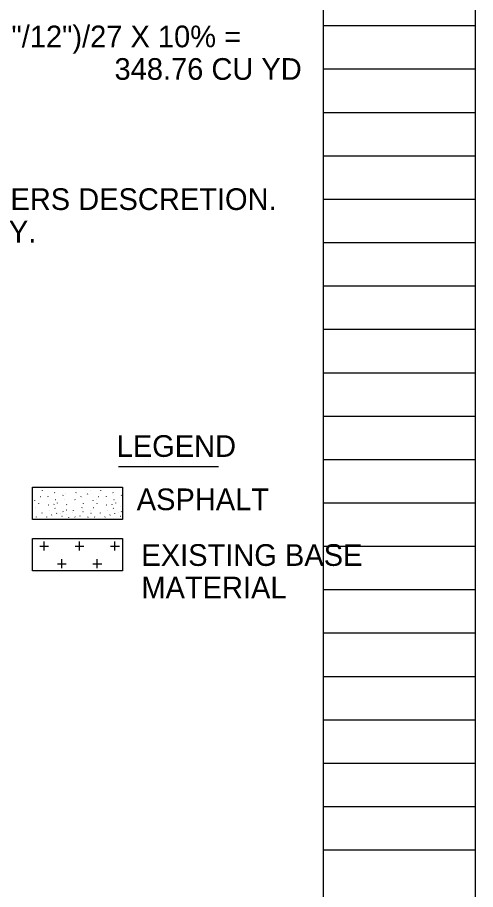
# Model space of a CAD drawing. Extents: x 0 to 34, y 0 to 22.
# Drawn here: x 22.21 to 25.16, y 10.52 to 16.15 of the extents above; entities that cross this region are included whole.
import ezdxf

# ---------------------------------------------------------------- set-up
doc = ezdxf.new("R2010")
doc.units = 0
for name, color, linetype in [('Default', 7, 'Continuous'), ('SH_Data', 7, 'Continuous'), ('SH_Text', 7, 'Continuous')]:
    doc.layers.add(name, color=color, linetype=linetype)

msp = doc.modelspace()

# ---------------------------------------------------------------- linework, layer by layer
at = {"layer": 'Default'}
for p, q in [((22.8569, 13.255), (23.5031, 13.255)), ((22.3542, 13.058), (22.3532, 13.0588)), ((22.3674, 13.0983), (22.3679, 13.1003)), ((22.4039, 13.0603), (22.4044, 13.062)), ((22.4462, 13.0853), (22.4452, 13.0862)), ((22.5, 13.0685), (22.498, 13.0675)), ((22.5185, 13.0802), (22.5175, 13.0813)), ((22.5829, 13.0837), (22.5835, 13.0858)), ((22.6169, 13.06), (22.6149, 13.0597)), ((22.6542, 13.077), (22.6542, 13.077)), ((22.6585, 13.0765), (22.6592, 13.0785)), ((22.6745, 13.1003), (22.6745, 13.1003)), ((22.73, 13.058), (22.729, 13.0588)), ((22.743, 13.0983), (22.7439, 13.1003)), ((22.7795, 13.0603), (22.7804, 13.062)), ((22.8222, 13.0853), (22.8212, 13.0862)), ((22.8759, 13.0685), (22.8739, 13.0675)), ((22.3182, 13.0338), (22.3187, 13.0355)), ((22.3437, 13.013), (22.3442, 13.0148)), ((22.4065, 13.0055), (22.4047, 13.005)), ((22.441, 13.0102), (22.4419, 13.0122)), ((22.453, 13.04), (22.451, 13.0395)), ((22.464, 13.0188), (22.4645, 13.0207)), ((22.5117, 13.041), (22.5109, 13.0422)), ((22.5227, 13.0075), (22.5234, 13.0093)), ((22.578, 13.0398), (22.577, 13.0408)), ((22.631, 13.013), (22.6319, 13.0148)), ((22.6939, 13.0338), (22.6947, 13.0355)), ((22.7144, 13.0385), (22.7144, 13.0385)), ((22.7197, 13.013), (22.7202, 13.0148)), ((22.7824, 13.0055), (22.7805, 13.005)), ((22.8169, 13.0102), (22.8177, 13.0122)), ((22.8289, 13.04), (22.8269, 13.0395)), ((22.8399, 13.0188), (22.8404, 13.0207)), ((22.305, 12.9503), (22.304, 12.9513)), ((22.321, 12.9873), (22.3192, 12.9868)), ((22.3662, 12.9543), (22.3652, 12.9553)), ((22.4129, 12.9695), (22.4134, 12.9712)), ((22.4489, 12.9833), (22.4479, 12.9845)), ((22.4585, 12.9513), (22.459, 12.9533)), ((22.4835, 12.9483), (22.4835, 12.9483)), ((22.5, 12.962), (22.499, 12.9632)), ((22.5239, 12.9727), (22.5219, 12.9723)), ((22.5579, 12.9582), (22.5579, 12.9582)), ((22.5665, 12.9712), (22.567, 12.973)), ((22.6232, 12.9893), (22.6212, 12.9887)), ((22.6304, 12.9628), (22.6285, 12.9623)), ((22.6739, 12.9737), (22.6739, 12.9737)), ((22.681, 12.9503), (22.68, 12.9513)), ((22.6969, 12.9873), (22.6949, 12.9868)), ((22.742, 12.9543), (22.741, 12.9553)), ((22.7887, 12.9695), (22.7894, 12.9712)), ((22.8249, 12.9833), (22.8237, 12.9845)), ((22.8344, 12.9513), (22.8349, 12.9533)), ((22.8557, 12.9573), (22.8557, 12.9573)), ((22.8677, 12.9988), (22.8677, 12.9988)), ((22.8759, 12.962), (22.8749, 12.9632)), ((22.3287, 12.9278), (22.3277, 12.929)), ((22.3947, 12.9275), (22.3955, 12.9295)), ((22.4265, 12.9412), (22.4272, 12.9432)), ((22.4775, 12.9143), (22.4784, 12.9138)), ((22.4784, 12.9138), (22.4789, 12.9133)), ((22.494, 12.9318), (22.493, 12.9328)), ((22.5225, 12.9417), (22.5214, 12.9427)), ((22.5382, 12.924), (22.5372, 12.925)), ((22.5774, 12.9278), (22.5762, 12.929)), ((22.6105, 12.9348), (22.6095, 12.9357)), ((22.6572, 12.932), (22.6572, 12.932)), ((22.6614, 12.926), (22.6595, 12.925)), ((22.7045, 12.9278), (22.7035, 12.929)), ((22.7705, 12.9275), (22.7714, 12.9295)), ((22.8024, 12.9412), (22.8032, 12.9432)), ((22.8534, 12.9143), (22.8542, 12.9138)), ((22.8542, 12.9138), (22.8547, 12.9133)), ((22.8699, 12.9318), (22.8689, 12.9328)), ((22.3497, 12.7412), (22.4067, 12.7412)), ((22.378, 12.7125), (22.378, 12.7697)), ((22.578, 12.7412), (22.6349, 12.7412)), ((22.6065, 12.7125), (22.6065, 12.7697)), ((22.8062, 12.7412), (22.8634, 12.7412)), ((22.8349, 12.7125), (22.8349, 12.7697)), ((22.4637, 12.6268), (22.5209, 12.6268)), ((22.4924, 12.5983), (22.4924, 12.6555)), ((22.6922, 12.6268), (22.7494, 12.6268)), ((22.7205, 12.5983), (22.7205, 12.6555))]:
    msp.add_line(p, q, dxfattribs=at)
for points in [[(22.303, 13.1212), (22.8832, 13.1212), (22.8832, 12.912), (22.303, 12.912)], [(22.303, 12.7905), (22.8832, 12.7905), (22.8832, 12.5812), (22.303, 12.5812)]]:
    msp.add_lwpolyline(points, close=True, dxfattribs=at)
at = {"layer": 'SH_Data'}
for p, q in [((24.18, 0.98), (24.18, 21.14)), ((25.16, 0.98), (25.16, 21.14)), ((24.18, 16.1), (25.16, 16.1)), ((24.18, 15.82), (25.16, 15.82)), ((24.18, 15.54), (25.16, 15.54)), ((24.18, 15.26), (25.16, 15.26)), ((24.18, 14.98), (25.16, 14.98)), ((24.18, 14.7), (25.16, 14.7)), ((24.18, 14.42), (25.16, 14.42)), ((24.18, 14.14), (25.16, 14.14)), ((24.18, 13.86), (25.16, 13.86)), ((24.18, 13.58), (25.16, 13.58)), ((24.18, 13.3), (25.16, 13.3)), ((24.18, 13.02), (25.16, 13.02)), ((24.18, 12.74), (25.16, 12.74)), ((24.18, 12.46), (25.16, 12.46)), ((24.18, 12.18), (25.16, 12.18)), ((24.18, 11.9), (25.16, 11.9)), ((24.18, 11.62), (25.16, 11.62)), ((24.18, 11.34), (25.16, 11.34)), ((24.18, 11.06), (25.16, 11.06)), ((24.18, 10.78), (25.16, 10.78))]:
    msp.add_line(p, q, dxfattribs=at)

# ---------------------------------------------------------------- texts
at = {"layer": 'Default'}
for s, p in [('LEGEND', (22.8457, 13.3166)), ('ASPHALT', (22.9751, 12.9726)), ('EXISTING BASE', (23.0052, 12.613)), ('MATERIAL', (23.0052, 12.403))]:
    msp.add_text(s, height=0.14, dxfattribs=at).set_placement(p)
at = {"layer": 'SH_Text'}
for s, p in [('10% OF THE TOTAL AREA = (125,554.71 SQFT X 6"/12")/27 X 10% =', (17.74, 15.96)), (' 348.76 CU YD', (22.78, 15.75)), ('PLACEMENT IS AT THE CONSTRUCTION ENGINEERS DESCRETION.', (17.74, 14.91)), ('QUANTITY CARRIED TO THE GENERAL SUMMARY.', (17.74, 14.7))]:
    msp.add_text(s, height=0.14, dxfattribs=at).set_placement(p)

doc.saveas('drawing.dxf')
